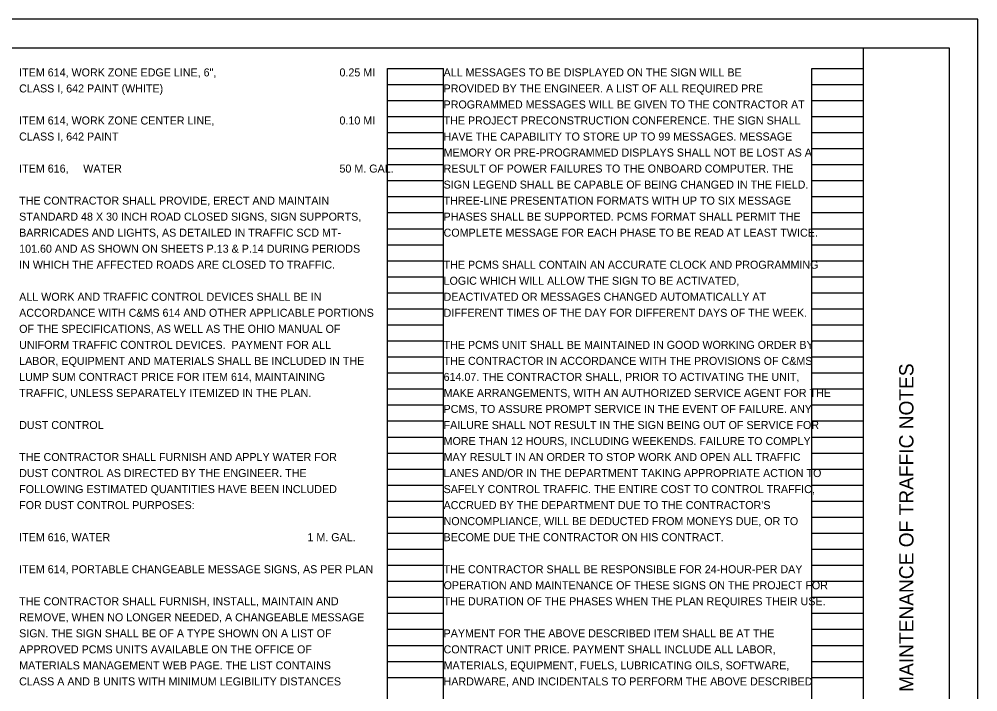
# Model space of a CAD drawing. Extents: x -50 to 112, y -27 to 22.
# Drawn here: x 56.24 to 73, y 10.25 to 22 of the extents above; entities that cross this region are included whole.
import ezdxf

# ---------------------------------------------------------------- set-up
doc = ezdxf.new("R2010")
doc.units = 0
for name, color, linetype in [('SC_Scratch1', 7, 'Continuous'), ('SH_Border', 7, 'Continuous'), ('SH_Cut_Line', 7, 'Continuous'), ('SH_Data', 7, 'Continuous'), ('SH_Text', 7, 'Continuous')]:
    doc.layers.add(name, color=color, linetype=linetype)

msp = doc.modelspace()

# ---------------------------------------------------------------- linework, layer by layer
at = {"layer": 'SC_Scratch1'}
for p, q in [((62.68, 0.98), (62.68, 21.14)), ((62.68, 21.14), (63.66, 21.14)), ((63.66, 0.98), (63.66, 21.14)), ((70.1, 0.98), (70.1, 21.14)), ((70.1, 21.14), (71, 21.14)), ((71, 0.98), (71, 21.14)), ((62.68, 20.86), (63.66, 20.86)), ((70.1, 20.86), (71, 20.86)), ((62.68, 20.58), (63.66, 20.58)), ((70.1, 20.58), (71, 20.58)), ((62.68, 20.3), (63.66, 20.3)), ((70.1, 20.3), (71, 20.3)), ((62.68, 20.02), (63.66, 20.02)), ((70.1, 20.02), (71, 20.02)), ((62.68, 19.74), (63.66, 19.74)), ((70.1, 19.74), (71, 19.74)), ((62.68, 19.46), (63.66, 19.46)), ((70.1, 19.46), (71, 19.46)), ((62.68, 19.18), (63.66, 19.18)), ((70.1, 19.18), (71, 19.18)), ((62.68, 18.9), (63.66, 18.9)), ((70.1, 18.9), (71, 18.9)), ((62.68, 18.62), (63.66, 18.62)), ((70.1, 18.62), (71, 18.62)), ((62.68, 18.34), (63.66, 18.34)), ((70.1, 18.34), (71, 18.34)), ((62.68, 18.06), (63.66, 18.06)), ((70.1, 18.06), (71, 18.06)), ((62.68, 17.78), (63.66, 17.78)), ((70.1, 17.78), (71, 17.78)), ((62.68, 17.5), (63.66, 17.5)), ((70.1, 17.5), (71, 17.5)), ((62.68, 17.22), (63.66, 17.22)), ((70.1, 17.22), (71, 17.22)), ((62.68, 16.94), (63.66, 16.94)), ((70.1, 16.94), (71, 16.94)), ((62.68, 16.66), (63.66, 16.66)), ((70.1, 16.66), (71, 16.66)), ((62.68, 16.38), (63.66, 16.38)), ((70.1, 16.38), (71, 16.38)), ((62.68, 16.1), (63.66, 16.1)), ((70.1, 16.1), (71, 16.1)), ((62.68, 15.82), (63.66, 15.82)), ((70.1, 15.82), (71, 15.82)), ((62.68, 15.54), (63.66, 15.54)), ((70.1, 15.54), (71, 15.54)), ((62.68, 15.26), (63.66, 15.26)), ((70.1, 15.26), (71, 15.26)), ((62.68, 14.98), (63.66, 14.98)), ((70.1, 14.98), (71, 14.98)), ((62.68, 14.7), (63.66, 14.7)), ((70.1, 14.7), (71, 14.7)), ((62.68, 14.42), (63.66, 14.42)), ((70.1, 14.42), (71, 14.42)), ((62.68, 14.14), (63.66, 14.14)), ((70.1, 14.14), (71, 14.14)), ((62.68, 13.86), (63.66, 13.86)), ((70.1, 13.86), (71, 13.86)), ((62.68, 13.58), (63.66, 13.58)), ((70.1, 13.58), (71, 13.58)), ((62.68, 13.3), (63.66, 13.3)), ((70.1, 13.3), (71, 13.3)), ((62.68, 13.02), (63.66, 13.02)), ((70.1, 13.02), (71, 13.02)), ((62.68, 12.74), (63.66, 12.74)), ((70.1, 12.74), (71, 12.74)), ((62.68, 12.46), (63.66, 12.46)), ((70.1, 12.46), (71, 12.46)), ((62.68, 12.18), (63.66, 12.18)), ((70.1, 12.18), (71, 12.18)), ((62.68, 11.9), (63.66, 11.9)), ((70.1, 11.9), (71, 11.9)), ((62.68, 11.62), (63.66, 11.62)), ((70.1, 11.62), (71, 11.62)), ((62.68, 11.34), (63.66, 11.34)), ((70.1, 11.34), (71, 11.34)), ((62.68, 11.06), (63.66, 11.06)), ((70.1, 11.06), (71, 11.06)), ((62.68, 10.78), (63.66, 10.78)), ((70.1, 10.78), (71, 10.78)), ((62.68, 10.5), (63.66, 10.5)), ((70.1, 10.5), (71, 10.5))]:
    msp.add_line(p, q, dxfattribs=at)
at = {"layer": 'SH_Border'}
msp.add_line((71, 0.5), (71, 21.5), dxfattribs=at)
msp.add_lwpolyline([(40.5, 21.5), (72.5, 21.5), (72.5, 0.5), (40.5, 0.5)], close=True, dxfattribs=at)
at = {"layer": 'SH_Cut_Line'}
msp.add_lwpolyline([(39, 0), (73, 0), (73, 22), (39, 22)], close=True, dxfattribs=at)

# ---------------------------------------------------------------- texts
at = {"layer": 'SH_Data'}
msp.add_text('MAINTENANCE OF TRAFFIC NOTES', height=0.25, rotation=90, dxfattribs=at).set_placement((71.875, 10.247))
at = {"layer": 'SH_Text'}
for s, p in [('ITEM 614, WORK ZONE EDGE LINE, 6", ', (56.24, 21)), ('0.25 MI', (61.84, 21)), ('ALL MESSAGES TO BE DISPLAYED ON THE SIGN WILL BE', (63.66, 21)), ('CLASS I, 642 PAINT (WHITE)', (56.24, 20.72)), ('PROVIDED BY THE ENGINEER. A LIST OF ALL REQUIRED PRE ', (63.66, 20.72)), ('PROGRAMMED MESSAGES WILL BE GIVEN TO THE CONTRACTOR AT ', (63.66, 20.44)), ('ITEM 614, WORK ZONE CENTER LINE, ', (56.24, 20.16)), ('0.10 MI', (61.84, 20.16)), ('THE PROJECT PRECONSTRUCTION CONFERENCE. THE SIGN SHALL ', (63.66, 20.16)), ('CLASS I, 642 PAINT', (56.24, 19.88)), ('HAVE THE CAPABILITY TO STORE UP TO 99 MESSAGES. MESSAGE ', (63.66, 19.88)), ('MEMORY OR PRE-PROGRAMMED DISPLAYS SHALL NOT BE LOST AS A ', (63.66, 19.6)), ('ITEM 616,', (56.24, 19.32)), ('WATER', (57.36, 19.32)), ('50 M. GAL.', (61.84, 19.32)), ('RESULT OF POWER FAILURES TO THE ONBOARD COMPUTER. THE ', (63.66, 19.32)), ('SIGN LEGEND SHALL BE CAPABLE OF BEING CHANGED IN THE FIELD. ', (63.66, 19.04)), ('THE CONTRACTOR SHALL PROVIDE, ERECT AND MAINTAIN ', (56.24, 18.76)), ('THREE-LINE PRESENTATION FORMATS WITH UP TO SIX MESSAGE ', (63.66, 18.76)), ('STANDARD 48 X 30 INCH ROAD CLOSED SIGNS, SIGN SUPPORTS, ', (56.24, 18.48)), ('PHASES SHALL BE SUPPORTED. PCMS FORMAT SHALL PERMIT THE ', (63.66, 18.48)), ('BARRICADES AND LIGHTS, AS DETAILED IN TRAFFIC SCD MT-', (56.24, 18.2)), ('COMPLETE MESSAGE FOR EACH PHASE TO BE READ AT LEAST TWICE.', (63.66, 18.2)), ('101.60 AND AS SHOWN ON SHEETS P.13 & P.14 DURING PERIODS ', (56.24, 17.92)), ('IN WHICH THE AFFECTED ROADS ARE CLOSED TO TRAFFIC.', (56.24, 17.64)), ('THE PCMS SHALL CONTAIN AN ACCURATE CLOCK AND PROGRAMMING ', (63.66, 17.64)), ('LOGIC WHICH WILL ALLOW THE SIGN TO BE ACTIVATED, ', (63.66, 17.36)), ('ALL WORK AND TRAFFIC CONTROL DEVICES SHALL BE IN ', (56.24, 17.08)), ('DEACTIVATED OR MESSAGES CHANGED AUTOMATICALLY AT ', (63.66, 17.08)), ('ACCORDANCE WITH C&MS 614 AND OTHER APPLICABLE PORTIONS ', (56.24, 16.8)), ('DIFFERENT TIMES OF THE DAY FOR DIFFERENT DAYS OF THE WEEK.', (63.66, 16.8)), ('OF THE SPECIFICATIONS, AS WELL AS THE OHIO MANUAL OF ', (56.24, 16.52)), ('UNIFORM TRAFFIC CONTROL DEVICES.  PAYMENT FOR ALL ', (56.24, 16.24)), ('THE PCMS UNIT SHALL BE MAINTAINED IN GOOD WORKING ORDER BY ', (63.66, 16.24)), ('LABOR, EQUIPMENT AND MATERIALS SHALL BE INCLUDED IN THE ', (56.24, 15.96)), ('THE CONTRACTOR IN ACCORDANCE WITH THE PROVISIONS OF C&MS ', (63.66, 15.96)), ('LUMP SUM CONTRACT PRICE FOR ITEM 614, MAINTAINING ', (56.24, 15.68)), ('614.07. THE CONTRACTOR SHALL, PRIOR TO ACTIVATING THE UNIT, ', (63.66, 15.68)), ('TRAFFIC, UNLESS SEPARATELY ITEMIZED IN THE PLAN.', (56.24, 15.4)), ('MAKE ARRANGEMENTS, WITH AN AUTHORIZED SERVICE AGENT FOR THE ', (63.66, 15.4)), ('PCMS, TO ASSURE PROMPT SERVICE IN THE EVENT OF FAILURE. ANY ', (63.66, 15.12)), ('DUST CONTROL', (56.24, 14.84)), ('FAILURE SHALL NOT RESULT IN THE SIGN BEING OUT OF SERVICE FOR ', (63.66, 14.84)), ('MORE THAN 12 HOURS, INCLUDING WEEKENDS. FAILURE TO COMPLY ', (63.66, 14.56)), ('THE CONTRACTOR SHALL FURNISH AND APPLY WATER FOR ', (56.24, 14.28)), ('MAY RESULT IN AN ORDER TO STOP WORK AND OPEN ALL TRAFFIC ', (63.66, 14.28)), ('DUST CONTROL AS DIRECTED BY THE ENGINEER. THE ', (56.24, 14)), ('LANES AND/OR IN THE DEPARTMENT TAKING APPROPRIATE ACTION TO ', (63.66, 14)), ('FOLLOWING ESTIMATED QUANTITIES HAVE BEEN INCLUDED ', (56.24, 13.72)), ('SAFELY CONTROL TRAFFIC. THE ENTIRE COST TO CONTROL TRAFFIC, ', (63.66, 13.72)), ('FOR DUST CONTROL PURPOSES:', (56.24, 13.44)), ("ACCRUED BY THE DEPARTMENT DUE TO THE CONTRACTOR'S ", (63.66, 13.44)), ('NONCOMPLIANCE, WILL BE DEDUCTED FROM MONEYS DUE, OR TO ', (63.66, 13.16)), ('ITEM 616, WATER', (56.24, 12.88)), ('1 M. GAL.', (61.28, 12.88)), ('BECOME DUE THE CONTRACTOR ON HIS CONTRACT.', (63.66, 12.88)), ('ITEM 614, PORTABLE CHANGEABLE MESSAGE SIGNS, AS PER PLAN', (56.24, 12.32)), ('THE CONTRACTOR SHALL BE RESPONSIBLE FOR 24-HOUR-PER DAY ', (63.66, 12.32)), ('OPERATION AND MAINTENANCE OF THESE SIGNS ON THE PROJECT FOR ', (63.66, 12.04)), ('THE CONTRACTOR SHALL FURNISH, INSTALL, MAINTAIN AND', (56.24, 11.76)), ('THE DURATION OF THE PHASES WHEN THE PLAN REQUIRES THEIR USE.', (63.66, 11.76)), ('REMOVE, WHEN NO LONGER NEEDED, A CHANGEABLE MESSAGE ', (56.24, 11.48)), ('SIGN. THE SIGN SHALL BE OF A TYPE SHOWN ON A LIST OF ', (56.24, 11.2)), ('PAYMENT FOR THE ABOVE DESCRIBED ITEM SHALL BE AT THE ', (63.66, 11.2)), ('APPROVED PCMS UNITS AVAILABLE ON THE OFFICE OF ', (56.24, 10.92)), ('CONTRACT UNIT PRICE. PAYMENT SHALL INCLUDE ALL LABOR, ', (63.66, 10.92)), ('MATERIALS MANAGEMENT WEB PAGE. THE LIST CONTAINS ', (56.24, 10.64)), ('MATERIALS, EQUIPMENT, FUELS, LUBRICATING OILS, SOFTWARE, ', (63.66, 10.64)), ('CLASS A AND B UNITS WITH MINIMUM LEGIBILITY DISTANCES ', (56.24, 10.36)), ('HARDWARE, AND INCIDENTALS TO PERFORM THE ABOVE DESCRIBED ', (63.66, 10.36))]:
    msp.add_text(s, height=0.14, dxfattribs=at).set_placement(p)

doc.saveas('drawing.dxf')
